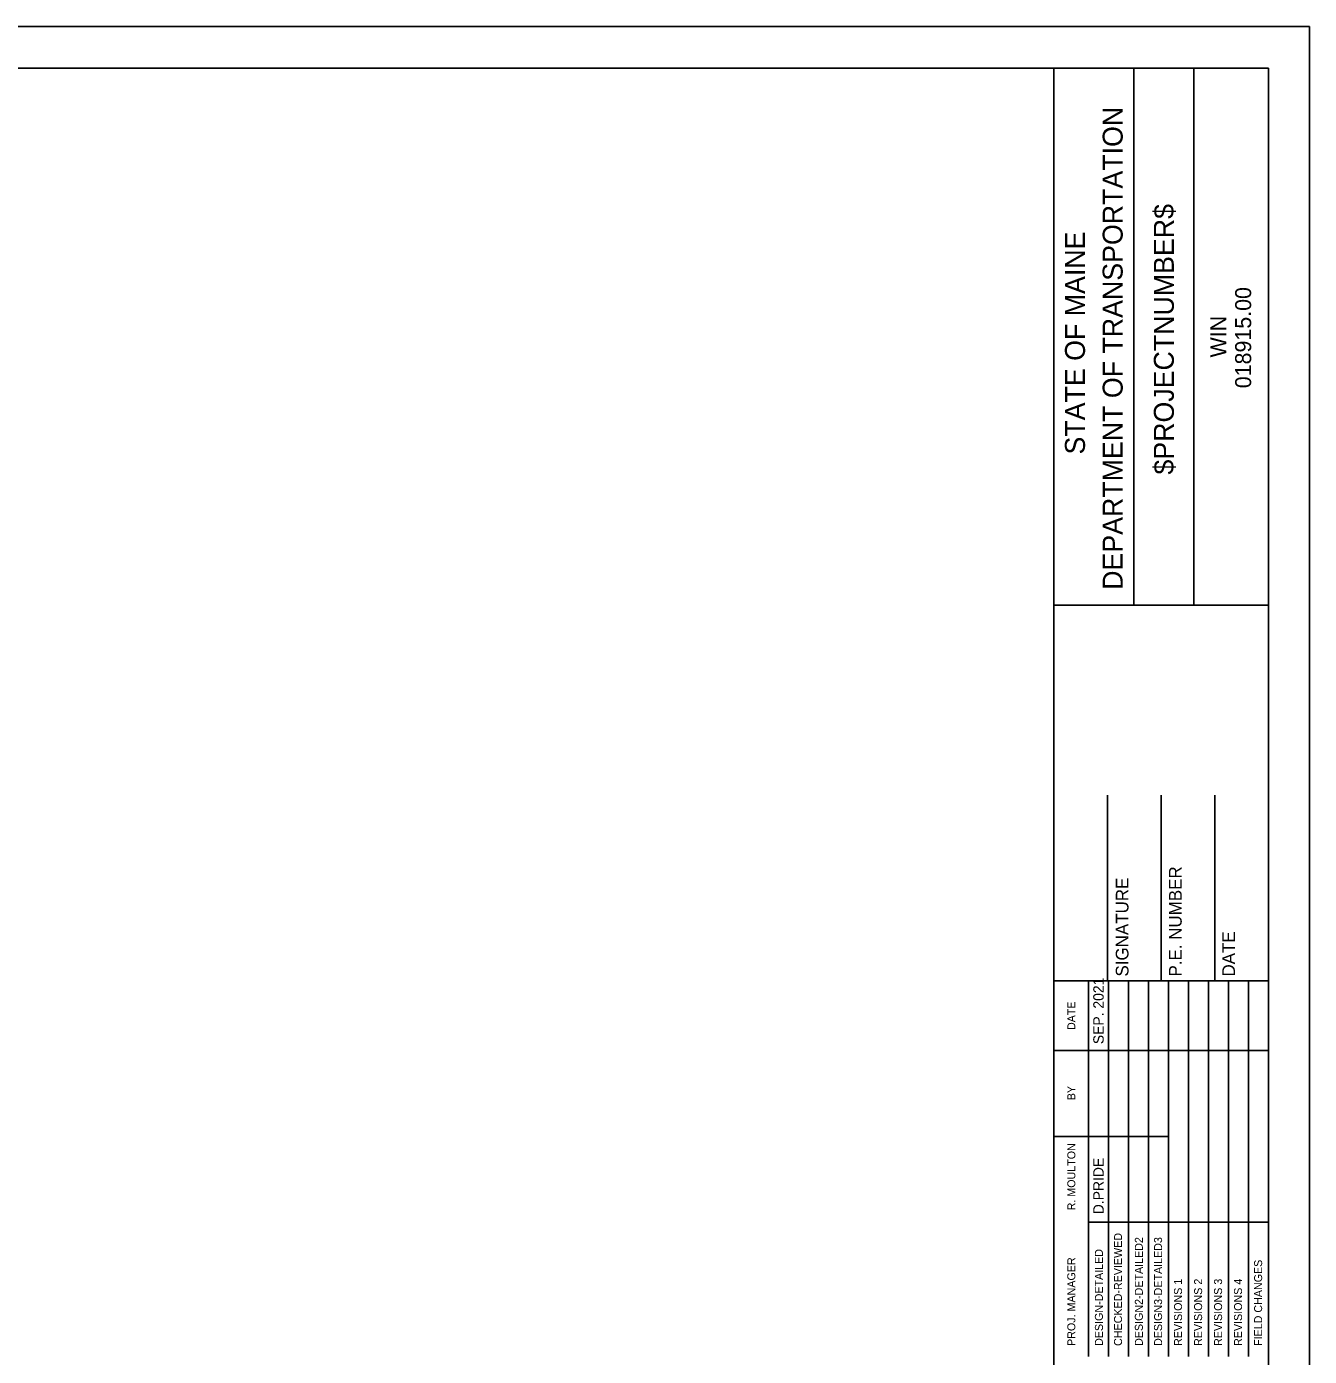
# Model space of a CAD drawing. Extents: x 1758647 to 1758990, y 442323 to 442543.
# Drawn here: x 1758867.1 to 1758986.6, y 442419.4 to 442543.3 of the extents above; entities that cross this region are included whole.
import ezdxf

# ---------------------------------------------------------------- set-up
doc = ezdxf.new("R2010")
doc.units = 0
doc.layers.add('BORDER', color=7, linetype='Continuous')
doc.layers.add('PLOT BOUNDARY', color=7, linetype='Continuous')

msp = doc.modelspace()

# ---------------------------------------------------------------- linework, layer by layer
at = {"layer": 'BORDER'}
for p, q in [((1758962.82, 442329.39), (1758962.82, 442539.39)), ((1758970.28, 442489.38), (1758970.28, 442539.38)), ((1758975.87, 442489.38), (1758975.87, 442539.38)), ((1758962.82, 442489.37), (1758982.82, 442489.37)), ((1758967.82, 442454.39), (1758967.82, 442471.69)), ((1758972.82, 442454.39), (1758972.82, 442471.69)), ((1758977.82, 442454.39), (1758977.82, 442471.69)), ((1758962.82, 442454.39), (1758982.82, 442454.39))]:
    msp.add_line(p, q, dxfattribs=at)
msp.add_lwpolyline([(1758662.82, 442329.39), (1758982.82, 442329.39), (1758982.82, 442539.39), (1758662.82, 442539.39)], close=True, dxfattribs=at)
for points in [[(1758966.05, 442447.89), (1758966.05, 442454.39)], [(1758967.92, 442419.4), (1758967.92, 442454.39)], [(1758969.78, 442454.39), (1758969.78, 442419.4)], [(1758971.64, 442419.4), (1758971.64, 442454.39)], [(1758973.51, 442419.4), (1758973.51, 442454.39)], [(1758975.37, 442419.4), (1758975.37, 442454.39)], [(1758977.23, 442419.4), (1758977.23, 442454.39)], [(1758979.1, 442419.4), (1758979.1, 442454.39)], [(1758980.96, 442419.4), (1758980.96, 442454.39)], [(1758966.05, 442419.4), (1758966.05, 442452.98)], [(1758962.82, 442447.89), (1758982.82, 442447.89)], [(1758962.82, 442439.89), (1758966.05, 442439.89)], [(1758966.05, 442439.89), (1758973.51, 442439.89)], [(1758966.05, 442431.89), (1758982.82, 442431.89)]]:
    msp.add_lwpolyline(points, dxfattribs=at)
at = {"layer": 'PLOT BOUNDARY'}
msp.add_lwpolyline([(1758646.64, 442323.27), (1758986.64, 442323.27), (1758986.64, 442543.27), (1758646.64, 442543.27)], close=True, dxfattribs=at)

# ---------------------------------------------------------------- texts
at = {"layer": 'BORDER'}
for s, height, p in [('DEPARTMENT OF TRANSPORTATION', 1.8635, (1758969.24, 442490.8)), ('$PROJECTNUMBER$', 1.8635, (1758974.01, 442501.54)), ('STATE OF MAINE', 1.8635, (1758965.73, 442503.41)), ('018915.00', 1.491, (1758981.21, 442509.58)), ('WIN', 1.491, (1758978.9, 442512.45)), ('SIGNATURE', 1.181, (1758969.78, 442454.78)), ('P.E. NUMBER', 1.1811, (1758974.74, 442454.78)), ('DATE', 1.181, (1758979.7, 442454.78)), ('SEP. 2021', 0.969, (1758967.47, 442448.48)), ('DATE', 0.743, (1758964.83, 442449.8)), ('BY', 0.743, (1758964.83, 442443.26)), ('R. MOULTON', 0.745, (1758964.83, 442433)), ('D.PRIDE', 0.969, (1758967.47, 442432.64)), ('CHECKED-REVIEWED', 0.7455, (1758969.18, 442420.37)), ('DESIGN2-DETAILED2', 0.7455, (1758971.12, 442420.37)), ('DESIGN3-DETAILED3', 0.7455, (1758972.91, 442420.37)), ('DESIGN-DETAILED', 0.7455, (1758967.4, 442420.37)), ('PROJ. MANAGER', 0.7455, (1758964.83, 442420.37)), ('FIELD CHANGES', 0.7455, (1758982.23, 442420.37)), ('REVISIONS 1', 0.7455, (1758974.77, 442420.37)), ('REVISIONS 2', 0.7455, (1758976.64, 442420.37)), ('REVISIONS 3', 0.7455, (1758978.5, 442420.37)), ('REVISIONS 4', 0.7455, (1758980.36, 442420.37))]:
    msp.add_text(s, height=height, rotation=90, dxfattribs=at).set_placement(p)

doc.saveas('drawing.dxf')
